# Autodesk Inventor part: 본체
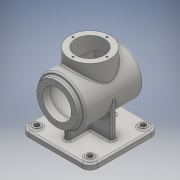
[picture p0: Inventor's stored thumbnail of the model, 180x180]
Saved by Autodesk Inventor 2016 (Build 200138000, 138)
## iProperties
Created: 2015-07
Part Number: 본체
Material: Generic
Document SubType Name: Modeling
Designer: Administrator
Density: 1 g/cm^3
Appearance: Default
Author: Administrator
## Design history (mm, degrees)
sketch "스케치1"
  geometry: L1 (-65, 65)-(65, 65); L2 (65, 65)-(65, -65); L3 (65, -65)-(-65, -65); L4 (-65, -65)-(-65, 65); 3 further points
  constraints: 8 end point, 2 midpoint, 2 parallel, 2 perpendicular, 1 horizontal, 1 horizontal alignment, 1 vertical alignment
  dimensions: "d0" = 130 distance of L1.start L1.end
extrude "돌출1" new body sketch "스케치1" distance "d1" = 10; taper "d2" = 0 deg
fillet "모깎기1" dims "d3" = 15
sketch "스케치2"
  geometry: C1 r 7.5 at (-50, 50); C2 r 7.5 at (50, 50); C3 r 7.5 at (-50, -50); C4 r 7.5 at (50, -50); A1 r 15 centre (-50, -50) between (-65, -50) and (-50, -65) reference; A2 r 15 centre (-50, 50) between (-50, 65) and (-65, 50) reference; A3 r 15 centre (50, 50) between (65, 50) and (50, 65) reference; A4 r 15 centre (50, -50) between (50, -65) and (65, -50) reference; 5 further points
  constraints: 8 coincident, 4 centre point
  dimensions: "d4" = 15 diameter of C1; "d5" = 15 diameter of C2; "d6" = 15 diameter of C3; "d7" = 15 diameter of C4
extrude "돌출2" join sketch "스케치2" distance "d8" = 3; taper "d9" = 0 deg
sketch "스케치4"
  geometry: C1 r 7.5 at (0, 100) reference; C2 r 7.5 at (0, 0) reference; C3 r 7.5 at (100, 0) reference; C4 r 7.5 at (100, 100) reference; 5 further points
  constraints: 4 coincident
hole "구멍1" sketch "스케치4" at (0, 100), (0, 0), (100, 0), (100, 100) diameter "d10" = 10; stored, may be unused: countersink angle "d14" = 90 deg, drill point angle "d16" = 118 deg; dims "d11" = 6, "d12" = 4, "d13" = 2, "d15" = 8
sketch "스케치6"
  geometry: L1 (-5, 45)-(5, 45); L2 (5, -45)-(-5, -45); L3 (45, 5)-(45, -5); L4 (-45, -5)-(-45, 5); L5 (-5, -45)-(-5, -5); L6 (-5, 5)-(-5, 45); L7 (-45, 5)-(-5, 5); L8 (5, 5)-(45, 5); L9 (5, 45)-(5, 5); L10 (5, -5)-(5, -45); L11 (45, -5)-(5, -5); L12 (-5, -5)-(-45, -5); 3 further points
  constraints: 24 end point, 10 parallel, 6 equal length, 4 perpendicular, 3 horizontal, 2 midpoint, 1 horizontal alignment, 1 vertical alignment
  dimensions: "d17" = 10 distance of L1.start L1.end; "d18" = 90 distance between parallel lines of L2 L1; "d19" = 90 distance between parallel lines of L3 L4; "d20" = 10 distance of L4.start L4.end
extrude "돌출3" join sketch "스케치6" distance "d21" = 68; taper "d22" = 0 deg
sketch "스케치7"
  geometry: C1 r 45 at (0, 78); 1 further point
  constraints: 1 centre point, 1 vertical alignment
  dimensions: "d23" = 90 diameter of C1; "d24" = 78 distance of point (0, 0) C1.centre
extrude "돌출4" join sketch "스케치7" stored distance "d25" = 110; taper "d26" = 0 deg
sketch "스케치9"
  geometry: C1 r 45 at (0, 0) reference; C2 r 38 at (0, 0); 1 further point
  constraints: 1 centre point, 1 coincident
  dimensions: "d27" = 76 diameter of C2
extrude "돌출5" join sketch "스케치9" distance "d28" = 7; taper "d29" = 0 deg
sketch "스케치10"
  geometry: L1 (0, 0)-(0, 140); L2 (0, 140)-(38, 140); L3 (38, 140)-(38, 95); L4 (38, 95)-(0, 95)
  constraints: 8 end point, 2 perpendicular, 1 horizontal, 1 point on line
  dimensions: "d31" = 140 distance of L1.start L1.end; "d32" = 76 diameter of L3 L1; "d33" = 45 distance of L2.end L3.end
revolve "회전1" sketch "스케치10" stored, may be unused: angle "d34" = 90 deg
sketch "스케치11"
  geometry: L1 (-62, 116)-(-62, 40) reference; L2 (-62, 78)-(55, 78); L3 (55, 33)-(55, 123) reference; L4 (-62, 105)-(-48, 105); L5 (-48, 105)-(-48, 118); L6 (-48, 118)-(48, 118); L7 (48, 118)-(48, 78); L8 (-62, 105)-(-62, 78); 1 further point
  constraints: 12 end point, 4 perpendicular, 2 midpoint, 2 point on line, 1 horizontal
  dimensions: "d35" = 14 distance of L4.start L4.end; "d36" = 54 diameter of L4 L2; "d37" = 80 diameter of L6 L2; "d38" = 96 distance of L5.end L6.end
revolve "회전2" sketch "스케치11" stored, may be unused: angle "d39" = 90 deg
sketch "스케치12"
  geometry: 2 further points
  constraints: 1 coincident
hole "구멍2" sketch "스케치12" at (0, 0) diameter "d40" = 54; stored, may be unused: countersink angle "d44" = 90 deg, drill point angle "d46" = 0 deg; dims "d41" = 6, "d42" = 4, "d43" = 2, "d45" = 8
sketch "스케치13"
  geometry: C1 r 27 at (0, 0) reference; A1 r 32 centre (0, 0) between (0, 32) and (-32, 0); 3 further points
  constraints: 4 point on circle, 2 horizontal alignment, 2 vertical alignment, 1 centre point, 1 coincident
  dimensions: "d47" = 64 diameter of A1
hole "구멍3" sketch "스케치13" at (0, 32), (-32, 0), (0, -32), (32, 0) diameter "d48" = 3.242; stored, may be unused: countersink angle "d52" = 90 deg, drill point angle "d54" = 118 deg; dims "d49" = 8, "d50" = 4, "d51" = 2, "d53" = 10
sketch "스케치14"
  geometry: A1 r 32 centre (0, 0) between (0, 32) and (-32, 0); 3 further points
  constraints: 4 point on circle, 2 horizontal alignment, 2 vertical alignment, 1 centre point, 1 coincident
  dimensions: "d55" = 64 diameter of A1
hole "구멍4" sketch "스케치14" at (0, 32), (-32, 0), (0, -32), (32, 0) diameter "d56" = 3.242; stored, may be unused: countersink angle "d60" = 90 deg, drill point angle "d62" = 118 deg; dims "d57" = 8, "d58" = 4, "d59" = 2, "d61" = 10
fillet "모깎기2" dims "d63" = 3
fillet "모깎기3" dims "d64" = 3
sketch "스케치15"
  geometry: 3 further points
  constraints: 1 coincident, 1 other
feature "엠보싱1" sketch "스케치15" dims "d0" = 130, "d65" = 0.5, "d66" = 0
node "솔리드1"
node "투영된 루프1"
node "투영된 루프2"
node "투영된 루프3"
